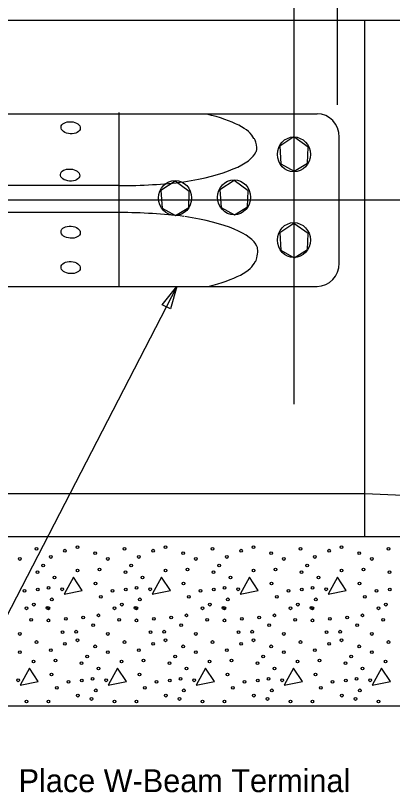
# Model space of a CAD drawing. Extents: x 0 to 34, y 0 to 22.
# Drawn here: x 26.922 to 29.227, y 8.365 to 13.117 of the extents above; entities that cross this region are included whole.
import ezdxf

# ---------------------------------------------------------------- set-up
doc = ezdxf.new("R2010")
doc.units = 0
doc.layers.add('ST_Details', color=7, linetype='Continuous')
doc.layers.add('ST_Text', color=7, linetype='Continuous')

msp = doc.modelspace()

# ---------------------------------------------------------------- linework, layer by layer
at = {"layer": 'ST_Details'}
for p, q in [((28.6245, 13.5688), (28.6245, 10.7396)), ((24.3078, 13.0897), (31.3683, 13.0897)), ((29.0587, 9.9282), (29.0587, 13.0897)), ((23.3887, 12.5167), (28.7673, 12.5167)), ((27.5567, 11.4602), (27.5567, 12.525)), ((28.6245, 12.3746), (28.5377, 12.3176)), ((28.7113, 12.3119), (28.6245, 12.3746)), ((28.9018, 11.6027), (28.9018, 12.3742)), ((28.5377, 12.3176), (28.5448, 12.2103)), ((28.7077, 12.2143), (28.7113, 12.3119)), ((28.5448, 12.2103), (28.6262, 12.1645)), ((28.6262, 12.1645), (28.7077, 12.2143)), ((27.5567, 12.0769), (3.3693, 12.0769)), ((27.898, 12.1037), (27.8112, 12.0467)), ((27.9847, 12.0411), (27.898, 12.1037)), ((28.2587, 12.1082), (28.1718, 12.0512)), ((28.3453, 12.0455), (28.2587, 12.1082)), ((27.8112, 12.0467), (27.8183, 11.9395)), ((27.9812, 11.9433), (27.9847, 12.0411)), ((28.1718, 12.0512), (28.179, 11.9439)), ((28.3418, 11.9479), (28.3453, 12.0455)), ((3.0439, 11.9903), (30.0612, 11.9903)), ((27.8183, 11.9395), (27.8997, 11.8936)), ((27.8997, 11.8936), (27.9812, 11.9433)), ((28.179, 11.9439), (28.2603, 11.8981)), ((28.2603, 11.8981), (28.3418, 11.9479)), ((27.5567, 11.9121), (3.3043, 11.9121)), ((28.6245, 11.8461), (28.5377, 11.7891)), ((28.7113, 11.7834), (28.6245, 11.8461)), ((28.5377, 11.7891), (28.5448, 11.6819)), ((28.7077, 11.6858), (28.7113, 11.7834)), ((28.5448, 11.6819), (28.6262, 11.636)), ((28.6262, 11.636), (28.7077, 11.6858)), ((23.9015, 11.4602), (28.7673, 11.4602)), ((24.3078, 10.1936), (29.0587, 10.1936)), ((29.0587, 10.1936), (31.3475, 10.0881)), ((31.401, 9.9282), (21.5127, 9.9292)), ((27.2765, 9.6826), (27.2203, 9.5769)), ((27.3305, 9.5997), (27.2765, 9.6826)), ((27.8148, 9.6826), (27.7585, 9.5769)), ((27.8688, 9.5997), (27.8148, 9.6826)), ((28.3532, 9.6826), (28.2968, 9.5769)), ((28.407, 9.5997), (28.3532, 9.6826)), ((28.8915, 9.6826), (28.8352, 9.5769)), ((28.9453, 9.5997), (28.8915, 9.6826)), ((27.2203, 9.5769), (27.3305, 9.5997)), ((27.7585, 9.5769), (27.8688, 9.5997)), ((28.2968, 9.5769), (28.407, 9.5997)), ((28.8352, 9.5769), (28.9453, 9.5997)), ((27.0073, 9.1258), (26.9512, 9.0202)), ((27.0613, 9.043), (27.0073, 9.1258)), ((27.5457, 9.1258), (27.4895, 9.0202)), ((27.5997, 9.043), (27.5457, 9.1258)), ((28.084, 9.1258), (28.0277, 9.0202)), ((28.138, 9.043), (28.084, 9.1258)), ((28.6223, 9.1258), (28.566, 9.0202)), ((28.6762, 9.043), (28.6223, 9.1258)), ((29.1607, 9.1258), (29.1043, 9.0202)), ((29.2145, 9.043), (29.1607, 9.1258)), ((26.9512, 9.0202), (27.0613, 9.043)), ((27.4895, 9.0202), (27.5997, 9.043)), ((28.0277, 9.0202), (28.138, 9.043)), ((28.566, 9.0202), (28.6762, 9.043)), ((29.1043, 9.0202), (29.2145, 9.043)), ((24.3072, 8.8955), (31.314, 8.8955))]:
    msp.add_line(p, q, dxfattribs=at)
for centre, major_axis, ratio, start_param, end_param in [((27.4638, 12.341), (-0.9201, 0), 0.25734, 3.245321, 3.962211), ((28.7673, 12.3742), (0, 0.1425), 0.944544, 4.712389, 6.283185), ((28.3858, 12.3254), (-0.0069, 0.0408), 0.255343, 3.141593, 6.283185), ((27.4775, 12.3098), (-0.9201, 0), 0.265372, 2.112257, 3.037851), ((27.5567, 12.3211), (-0.9201, 0), 0.265372, 1.570796, 2.014581), ((27.5567, 11.6679), (0.9201, 0), 0.265372, 1.127015, 1.570796), ((27.4832, 11.6795), (0.9201, 0), 0.265372, 0.104113, 1.029331), ((28.3934, 11.6593), (-0.0049, -0.0456), 0.189002, 0, 3.141593), ((27.4734, 11.639), (0.9201, 0), 0.265372, 5.462567, 6.179461), ((28.7673, 11.6027), (0, 0.1425), 0.944544, 3.141593, 4.712389)]:
    msp.add_ellipse(centre, major_axis=major_axis, ratio=ratio, start_param=start_param, end_param=end_param, dxfattribs=at)
for centre, major_axis, ratio in [((27.2592, 12.4312), (-0.059, 0.0039), 0.623742), ((28.6245, 12.2679), (0, 0.1068), 0.944544), ((27.2553, 12.1418), (-0.059, 0.0039), 0.623742), ((27.898, 12.0014), (0, 0.1068), 0.944544), ((28.2587, 12.0059), (0, 0.1068), 0.944544), ((28.6245, 11.7438), (0, 0.1068), 0.944544), ((27.2592, 11.792), (-0.059, 0.0039), 0.623742), ((27.2592, 11.5755), (-0.059, 0.0039), 0.623742), ((27.05, 9.8547), (0, 0.00862), 0.944544), ((27.2244, 9.8439), (0, 0.00862), 0.944544), ((27.3005, 9.8654), (0, 0.00862), 0.944544), ((27.5883, 9.8547), (0, 0.00862), 0.944544), ((27.7628, 9.8439), (0, 0.00862), 0.944544), ((27.8388, 9.8654), (0, 0.00862), 0.944544), ((28.1267, 9.8547), (0, 0.00862), 0.944544), ((28.3011, 9.8439), (0, 0.00862), 0.944544), ((28.3771, 9.8654), (0, 0.00862), 0.944544), ((28.665, 9.8547), (0, 0.00862), 0.944544), ((28.8394, 9.8439), (0, 0.00862), 0.944544), ((28.9155, 9.8654), (0, 0.00862), 0.944544), ((29.2033, 9.8547), (0, 0.00862), 0.944544), ((26.9482, 9.7931), (0, 0.00862), 0.944544), ((27.1372, 9.8054), (0, 0.00862), 0.944544), ((27.4095, 9.8285), (0, 0.00862), 0.944544), ((27.4865, 9.7931), (0, 0.00862), 0.944544), ((27.6756, 9.8054), (0, 0.00862), 0.944544), ((27.9478, 9.8285), (0, 0.00862), 0.944544), ((28.0248, 9.7931), (0, 0.00862), 0.944544), ((28.2139, 9.8054), (0, 0.00862), 0.944544), ((28.4862, 9.8285), (0, 0.00862), 0.944544), ((28.5631, 9.7931), (0, 0.00862), 0.944544), ((28.7522, 9.8054), (0, 0.00862), 0.944544), ((29.0245, 9.8285), (0, 0.00862), 0.944544), ((29.1014, 9.7931), (0, 0.00862), 0.944544), ((27.0909, 9.7537), (0, 0.00862), 0.944544), ((27.6293, 9.7537), (0, 0.00862), 0.944544), ((28.1676, 9.7537), (0, 0.00862), 0.944544), ((28.7059, 9.7537), (0, 0.00862), 0.944544), ((27.056, 9.7122), (0, 0.00862), 0.944544), ((27.3017, 9.723), (0, 0.00862), 0.944544), ((27.4355, 9.7291), (0, 0.00862), 0.944544), ((27.5944, 9.7122), (0, 0.00862), 0.944544), ((27.84, 9.723), (0, 0.00862), 0.944544), ((27.9738, 9.7291), (0, 0.00862), 0.944544), ((28.1327, 9.7122), (0, 0.00862), 0.944544), ((28.3783, 9.723), (0, 0.00862), 0.944544), ((28.5121, 9.7291), (0, 0.00862), 0.944544), ((28.671, 9.7122), (0, 0.00862), 0.944544), ((28.9166, 9.723), (0, 0.00862), 0.944544), ((29.0504, 9.7291), (0, 0.00862), 0.944544), ((29.2093, 9.7122), (0, 0.00862), 0.944544), ((27.1607, 9.6798), (0, 0.00862), 0.944544), ((27.4107, 9.643), (0, 0.00862), 0.944544), ((27.6991, 9.6798), (0, 0.00862), 0.944544), ((27.949, 9.643), (0, 0.00862), 0.944544), ((28.2374, 9.6798), (0, 0.00862), 0.944544), ((28.4873, 9.643), (0, 0.00862), 0.944544), ((28.7757, 9.6798), (0, 0.00862), 0.944544), ((29.0256, 9.643), (0, 0.00862), 0.944544), ((26.9771, 9.5983), (0, 0.00862), 0.944544), ((27.0575, 9.606), (0, 0.00862), 0.944544), ((27.1244, 9.6168), (0, 0.00862), 0.944544), ((27.2072, 9.6075), (0, 0.00862), 0.944544), ((27.5154, 9.5983), (0, 0.00862), 0.944544), ((27.5958, 9.606), (0, 0.00862), 0.944544), ((27.6627, 9.6168), (0, 0.00862), 0.944544), ((27.7455, 9.6075), (0, 0.00862), 0.944544), ((28.0537, 9.5983), (0, 0.00862), 0.944544), ((28.1341, 9.606), (0, 0.00862), 0.944544), ((28.201, 9.6168), (0, 0.00862), 0.944544), ((28.2838, 9.6075), (0, 0.00862), 0.944544), ((28.592, 9.5983), (0, 0.00862), 0.944544), ((28.6724, 9.606), (0, 0.00862), 0.944544), ((28.7393, 9.6168), (0, 0.00862), 0.944544), ((28.8221, 9.6075), (0, 0.00862), 0.944544), ((29.1303, 9.5983), (0, 0.00862), 0.944544), ((29.2107, 9.606), (0, 0.00862), 0.944544), ((27.1433, 9.546), (0, 0.00862), 0.944544), ((27.4442, 9.5614), (0, 0.00862), 0.944544), ((27.6816, 9.546), (0, 0.00862), 0.944544), ((27.9825, 9.5614), (0, 0.00862), 0.944544), ((28.2199, 9.546), (0, 0.00862), 0.944544), ((28.5208, 9.5614), (0, 0.00862), 0.944544), ((28.7582, 9.546), (0, 0.00862), 0.944544), ((29.0591, 9.5614), (0, 0.00862), 0.944544), ((27.0342, 9.5137), (0, 0.00862), 0.944544), ((27.5726, 9.5137), (0, 0.00862), 0.944544), ((28.1109, 9.5137), (0, 0.00862), 0.944544), ((28.6492, 9.5137), (0, 0.00862), 0.944544), ((29.1875, 9.5137), (0, 0.00862), 0.944544), ((26.9889, 9.4915), (0, 0.00862), 0.944544), ((27.1171, 9.4937), (0, 0.00862), 0.944544), ((27.1227, 9.4915), (0, 0.00862), 0.944544), ((27.5272, 9.4915), (0, 0.00862), 0.944544), ((27.6555, 9.4937), (0, 0.00862), 0.944544), ((27.661, 9.4915), (0, 0.00862), 0.944544), ((28.0656, 9.4915), (0, 0.00862), 0.944544), ((28.1938, 9.4937), (0, 0.00862), 0.944544), ((28.1993, 9.4915), (0, 0.00862), 0.944544), ((28.6039, 9.4915), (0, 0.00862), 0.944544), ((28.7321, 9.4937), (0, 0.00862), 0.944544), ((28.7376, 9.4915), (0, 0.00862), 0.944544), ((29.1422, 9.4915), (0, 0.00862), 0.944544), ((27.018, 9.4207), (0, 0.00862), 0.944544), ((27.1227, 9.4176), (0, 0.00862), 0.944544), ((27.2303, 9.4269), (0, 0.00862), 0.944544), ((27.3353, 9.4346), (0, 0.00862), 0.944544), ((27.4284, 9.4484), (0, 0.00862), 0.944544), ((27.5563, 9.4207), (0, 0.00862), 0.944544), ((27.661, 9.4176), (0, 0.00862), 0.944544), ((27.7686, 9.4269), (0, 0.00862), 0.944544), ((27.8736, 9.4346), (0, 0.00862), 0.944544), ((27.9667, 9.4484), (0, 0.00862), 0.944544), ((28.0946, 9.4207), (0, 0.00862), 0.944544), ((28.1993, 9.4176), (0, 0.00862), 0.944544), ((28.3069, 9.4269), (0, 0.00862), 0.944544), ((28.412, 9.4346), (0, 0.00862), 0.944544), ((28.505, 9.4484), (0, 0.00862), 0.944544), ((28.6329, 9.4207), (0, 0.00862), 0.944544), ((28.7376, 9.4176), (0, 0.00862), 0.944544), ((28.8452, 9.4269), (0, 0.00862), 0.944544), ((28.9503, 9.4346), (0, 0.00862), 0.944544), ((29.0433, 9.4484), (0, 0.00862), 0.944544), ((29.1712, 9.4207), (0, 0.00862), 0.944544), ((27.3964, 9.3884), (0, 0.00862), 0.944544), ((27.9347, 9.3884), (0, 0.00862), 0.944544), ((28.4731, 9.3884), (0, 0.00862), 0.944544), ((29.0114, 9.3884), (0, 0.00862), 0.944544), ((26.9482, 9.3345), (0, 0.00862), 0.944544), ((27.2099, 9.3453), (0, 0.00862), 0.944544), ((27.2933, 9.3483), (0, 0.00862), 0.944544), ((27.4865, 9.3345), (0, 0.00862), 0.944544), ((27.7482, 9.3453), (0, 0.00862), 0.944544), ((27.8316, 9.3483), (0, 0.00862), 0.944544), ((28.0248, 9.3345), (0, 0.00862), 0.944544), ((28.2865, 9.3453), (0, 0.00862), 0.944544), ((28.3699, 9.3483), (0, 0.00862), 0.944544), ((28.5631, 9.3345), (0, 0.00862), 0.944544), ((28.8248, 9.3453), (0, 0.00862), 0.944544), ((28.9082, 9.3483), (0, 0.00862), 0.944544), ((29.1014, 9.3345), (0, 0.00862), 0.944544), ((27.05, 9.2848), (0, 0.00862), 0.944544), ((27.2244, 9.274), (0, 0.00862), 0.944544), ((27.3005, 9.2955), (0, 0.00862), 0.944544), ((27.5883, 9.2848), (0, 0.00862), 0.944544), ((27.7628, 9.274), (0, 0.00862), 0.944544), ((27.8388, 9.2955), (0, 0.00862), 0.944544), ((28.1267, 9.2848), (0, 0.00862), 0.944544), ((28.3011, 9.274), (0, 0.00862), 0.944544), ((28.3771, 9.2955), (0, 0.00862), 0.944544), ((28.665, 9.2848), (0, 0.00862), 0.944544), ((28.8394, 9.274), (0, 0.00862), 0.944544), ((28.9155, 9.2955), (0, 0.00862), 0.944544), ((29.2033, 9.2848), (0, 0.00862), 0.944544), ((26.9482, 9.2232), (0, 0.00862), 0.944544), ((27.1372, 9.2355), (0, 0.00862), 0.944544), ((27.4095, 9.2586), (0, 0.00862), 0.944544), ((27.4865, 9.2232), (0, 0.00862), 0.944544), ((27.6756, 9.2355), (0, 0.00862), 0.944544), ((27.9478, 9.2586), (0, 0.00862), 0.944544), ((28.0248, 9.2232), (0, 0.00862), 0.944544), ((28.2139, 9.2355), (0, 0.00862), 0.944544), ((28.4862, 9.2586), (0, 0.00862), 0.944544), ((28.5631, 9.2232), (0, 0.00862), 0.944544), ((28.7522, 9.2355), (0, 0.00862), 0.944544), ((29.0245, 9.2586), (0, 0.00862), 0.944544), ((29.1014, 9.2232), (0, 0.00862), 0.944544), ((27.0325, 9.1662), (0, 0.00862), 0.944544), ((27.1663, 9.1724), (0, 0.00862), 0.944544), ((27.3601, 9.197), (0, 0.00862), 0.944544), ((27.5709, 9.1662), (0, 0.00862), 0.944544), ((27.7046, 9.1724), (0, 0.00862), 0.944544), ((27.8984, 9.197), (0, 0.00862), 0.944544), ((28.1092, 9.1662), (0, 0.00862), 0.944544), ((28.2429, 9.1724), (0, 0.00862), 0.944544), ((28.4367, 9.197), (0, 0.00862), 0.944544), ((28.6475, 9.1662), (0, 0.00862), 0.944544), ((28.7812, 9.1724), (0, 0.00862), 0.944544), ((28.975, 9.197), (0, 0.00862), 0.944544), ((29.1858, 9.1662), (0, 0.00862), 0.944544), ((27.3252, 9.1555), (0, 0.00862), 0.944544), ((27.4299, 9.1231), (0, 0.00862), 0.944544), ((27.8635, 9.1555), (0, 0.00862), 0.944544), ((27.9682, 9.1231), (0, 0.00862), 0.944544), ((28.4018, 9.1555), (0, 0.00862), 0.944544), ((28.5065, 9.1231), (0, 0.00862), 0.944544), ((28.9401, 9.1555), (0, 0.00862), 0.944544), ((29.0448, 9.1231), (0, 0.00862), 0.944544), ((27.1416, 9.0863), (0, 0.00862), 0.944544), ((27.6799, 9.0863), (0, 0.00862), 0.944544), ((28.2182, 9.0863), (0, 0.00862), 0.944544), ((28.7565, 9.0863), (0, 0.00862), 0.944544), ((26.9381, 9.0508), (0, 0.00862), 0.944544), ((27.2463, 9.0416), (0, 0.00862), 0.944544), ((27.3266, 9.0493), (0, 0.00862), 0.944544), ((27.3936, 9.0601), (0, 0.00862), 0.944544), ((27.4764, 9.0508), (0, 0.00862), 0.944544), ((27.7846, 9.0416), (0, 0.00862), 0.944544), ((27.8649, 9.0493), (0, 0.00862), 0.944544), ((27.9319, 9.0601), (0, 0.00862), 0.944544), ((28.0147, 9.0508), (0, 0.00862), 0.944544), ((28.3229, 9.0416), (0, 0.00862), 0.944544), ((28.4033, 9.0493), (0, 0.00862), 0.944544), ((28.4702, 9.0601), (0, 0.00862), 0.944544), ((28.553, 9.0508), (0, 0.00862), 0.944544), ((28.8612, 9.0416), (0, 0.00862), 0.944544), ((28.9416, 9.0493), (0, 0.00862), 0.944544), ((29.0085, 9.0601), (0, 0.00862), 0.944544), ((29.0913, 9.0508), (0, 0.00862), 0.944544), ((27.175, 9.0047), (0, 0.00862), 0.944544), ((27.4124, 8.9893), (0, 0.00862), 0.944544), ((27.7133, 9.0047), (0, 0.00862), 0.944544), ((27.9507, 8.9893), (0, 0.00862), 0.944544), ((28.2516, 9.0047), (0, 0.00862), 0.944544), ((28.489, 8.9893), (0, 0.00862), 0.944544), ((28.7899, 9.0047), (0, 0.00862), 0.944544), ((29.0273, 8.9893), (0, 0.00862), 0.944544), ((27.3034, 8.957), (0, 0.00862), 0.944544), ((27.3863, 8.937), (0, 0.00862), 0.944544), ((27.8417, 8.957), (0, 0.00862), 0.944544), ((27.9246, 8.937), (0, 0.00862), 0.944544), ((28.38, 8.957), (0, 0.00862), 0.944544), ((28.4629, 8.937), (0, 0.00862), 0.944544), ((28.9183, 8.957), (0, 0.00862), 0.944544), ((29.0012, 8.937), (0, 0.00862), 0.944544), ((26.9889, 8.9216), (0, 0.00862), 0.944544), ((27.1227, 8.9216), (0, 0.00862), 0.944544), ((27.5272, 8.9216), (0, 0.00862), 0.944544), ((27.661, 8.9216), (0, 0.00862), 0.944544), ((28.0656, 8.9216), (0, 0.00862), 0.944544), ((28.1993, 8.9216), (0, 0.00862), 0.944544), ((28.6039, 8.9216), (0, 0.00862), 0.944544), ((28.7376, 8.9216), (0, 0.00862), 0.944544), ((29.1422, 8.9216), (0, 0.00862), 0.944544)]:
    msp.add_ellipse(centre, major_axis=major_axis, ratio=ratio, dxfattribs=at)
at = {"layer": 'ST_Text'}
msp.add_line((28.8912, 12.5703), (28.8912, 14.5177), dxfattribs=at)
msp.add_lwpolyline([(27.9082, 11.4602), (26.3382, 8.4221), (26.7987, 8.4221)], dxfattribs=at)
msp.add_lwpolyline([(27.8688, 11.3229), (27.819, 11.3486), (27.9082, 11.4602)], close=True, dxfattribs=at)

# ---------------------------------------------------------------- texts
msp.add_text('Place W-Beam Terminal', height=0.14, dxfattribs=at).set_placement((26.941, 8.3668))

doc.saveas('drawing.dxf')
